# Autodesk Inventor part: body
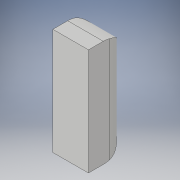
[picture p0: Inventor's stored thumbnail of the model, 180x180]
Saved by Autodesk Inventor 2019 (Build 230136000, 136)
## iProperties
Created: 2020-08
Part Number: body
Material: 一般
Document SubType Name: Modeling
Designer: kikut
Density: 1 g/cm^3
Appearance: 既定
Author: kikut
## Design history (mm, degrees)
sketch "スケッチ1"
  geometry: L1 (-0.06, -0.18)-(0.06, -0.18); L2 (0.06, -0.18)-(0.06, 0.18); L3 (0.06, 0.18)-(-0.06, 0.18); L4 (-0.06, 0.18)-(-0.06, -0.18); L5 (-0.06, -0.18)-(0.06, 0.18); L6 (0.06, -0.18)-(-0.06, 0.18); 1 further point
  constraints: 12 end point, 2 midpoint, 2 parallel, 1 horizontal, 1 perpendicular
  dimensions: "d0" = 0.36 distance of L1.end L2.end; "d1" = 0.12 distance of L2.end L3.end
extrude "押し出し1" new body sketch "スケッチ1" distance "d2" = 0.06; taper "d4" = 0 deg; dims "d3" = 0.07, "d5" = 0
fillet "フィレット2" dims "d7" = 0.08
sketch "スケッチ2"
  geometry: L1 (0.12, -0.05)-(0.12, -0.13) reference; L2 (0.12, -0.07)-(0.14, -0.07); L3 (0.14, -0.07)-(0.14, -0.17); L4 (0.14, -0.17)-(-0.02, -0.17); L5 (-0.02, -0.17)-(-0.02, -0.07); L6 (-0.02, -0.07)-(0, -0.07); L7 (0, 0)-(0.12, 0) reference; A1 r 0.06 centre (0.06, -0.07) between (0, -0.07) and (0.12, -0.07); 1 further point
  constraints: 10 end point, 4 perpendicular, 2 point on circle, 2 point on line, 1 centre point, 1 horizontal
  dimensions: "d8" = 0.06 radius of A1; "d9" = 0.02 distance of L5.end L6.end; "d10" = 0.02 distance of L2.start L2.end; "d11" = 0.16 distance of L3.end L4.end; "d12" = 0.1 distance of L2.end L3.end; "d13" = 0.13 dimension on A1 L7
extrude "押し出し2" cut sketch "スケッチ2" extent not by distance; stored distance "d14" = 0.06; taper "d15" = 0 deg
node "ソリッド1"
